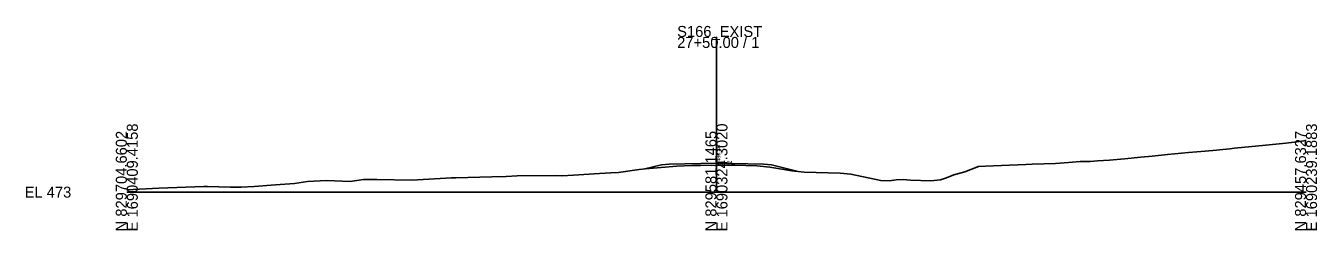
# Model space of a CAD drawing. Extents: x 1621104 to 1621433, y 1192880 to 1199414.
# Drawn here: x 1621104.2 to 1621432.7, y 1193379.5 to 1193431.6 of the extents above; entities that cross this region are included whole.
import ezdxf

# ---------------------------------------------------------------- set-up
doc = ezdxf.new("R2010")
doc.units = 0
for name, color, linetype in [('RD_GPK_XS_Cell', 7, 'Continuous'), ('RD_XS_EarthShd', 7, 'Continuous'), ('RD_XS_ExGround', 7, 'Continuous'), ('RD_XS_Pave', 7, 'Continuous'), ('RD_XS_TieSlope', 7, 'Continuous'), ('RD_XS_TX_Elev_EX', 7, 'Continuous'), ('RD_XS_TX_Elev_PR', 7, 'Continuous')]:
    doc.layers.add(name, color=color, linetype=linetype)

msp = doc.modelspace()

# ---------------------------------------------------------------- linework, layer by layer
at = {"layer": 'RD_GPK_XS_Cell'}
for p, q in [((1621279.86, 1193389.24), (1621279.86, 1193428.77)), ((1621129.86, 1193389.24), (1621279.86, 1193389.24)), ((1621279.86, 1193389.24), (1621429.86, 1193389.24))]:
    msp.add_line(p, q, dxfattribs=at)
at = {"layer": 'RD_XS_EarthShd'}
for p, q in [((1621267.86, 1193396.35), (1621265.86, 1193396.19)), ((1621291.86, 1193396.35), (1621293.86, 1193396.19))]:
    msp.add_line(p, q, dxfattribs=at)
at = {"layer": 'RD_XS_ExGround'}
msp.add_lwpolyline([(1621129.86, 1193389.85), (1621137.99, 1193390.24), (1621149.45, 1193390.64), (1621150.36, 1193390.64), (1621156.17, 1193390.47), (1621158.92, 1193390.52), (1621162.22, 1193390.64), (1621167.69, 1193391.08), (1621172.54, 1193391.4), (1621175.85, 1193391.92), (1621180.65, 1193392.22), (1621186.67, 1193391.99), (1621190.08, 1193392.46), (1621193.45, 1193392.47), (1621202.38, 1193392.27), (1621212.5, 1193392.88), (1621213.14, 1193392.91), (1621213.58, 1193392.88), (1621222.71, 1193393.17), (1621226.37, 1193393.24), (1621229.13, 1193393.43), (1621239.03, 1193393.44), (1621240.57, 1193393.43), (1621243.49, 1193393.55), (1621250.14, 1193394.02), (1621253, 1193394.14), (1621254.98, 1193394.27), (1621260.21, 1193395.03), (1621261.85, 1193395.15), (1621269.76, 1193395.87), (1621273.61, 1193396.06), (1621275.84, 1193396.06), (1621279.86, 1193396.08), (1621282.56, 1193396.09), (1621284.56, 1193396.13), (1621290.11, 1193395.94), (1621293.47, 1193395.62), (1621299.02, 1193394.7), (1621302.17, 1193394.31), (1621311.36, 1193394.11), (1621314.08, 1193393.81), (1621321.67, 1193392.18), (1621323.81, 1193392.11), (1621325.56, 1193392.35), (1621327.35, 1193392.49), (1621329.2, 1193392.29), (1621334.39, 1193392.12), (1621336.9, 1193392.34), (1621338.39, 1193392.9), (1621340.25, 1193393.66), (1621343.06, 1193394.4), (1621346.53, 1193395.77), (1621348.31, 1193395.83), (1621352.39, 1193395.99), (1621358.58, 1193396.28), (1621360.17, 1193396.37), (1621366.12, 1193396.56), (1621369.43, 1193396.81), (1621372.43, 1193397.04), (1621374.94, 1193397.05), (1621376.83, 1193397.19), (1621379.88, 1193397.37), (1621383.69, 1193397.74), (1621387.84, 1193398.15), (1621390.69, 1193398.43), (1621394.61, 1193398.81), (1621399.92, 1193399.3), (1621404.23, 1193399.71), (1621407.05, 1193399.94), (1621407.83, 1193400.01), (1621410.48, 1193400.27), (1621411.69, 1193400.41), (1621419.63, 1193401.24), (1621424.76, 1193401.73), (1621425.39, 1193401.79), (1621426.9, 1193401.99), (1621429.86, 1193402.41)], dxfattribs=at)
at = {"layer": 'RD_XS_Pave'}
for p, q in [((1621267.86, 1193396.35), (1621279.86, 1193396.59)), ((1621279.86, 1193396.59), (1621291.86, 1193396.35))]:
    msp.add_line(p, q, dxfattribs=at)
at = {"layer": 'RD_XS_TieSlope'}
for p, q in [((1621265.86, 1193396.19), (1621261.63, 1193395.14)), ((1621293.86, 1193396.19), (1621300.62, 1193394.5))]:
    msp.add_line(p, q, dxfattribs=at)

# ---------------------------------------------------------------- texts
at = {"layer": 'RD_GPK_XS_Cell'}
for s, p in [('S166_EXIST', (1621269.86, 1193428.77)), ('27+50.00 / 1', (1621269.86, 1193425.97)), ('EL 473', (1621103.86, 1193387.84))]:
    msp.add_text(s, height=2.8, dxfattribs=at).set_placement(p)
for s, p in [('N 829704.6602', (1621129.86, 1193379.24)), ('E 1690409.4158', (1621132.66, 1193379.24)), ('N 829581.1465', (1621279.86, 1193379.24)), ('E 1690324.3020', (1621282.66, 1193379.24)), ('N 829457.6327', (1621429.86, 1193379.24)), ('E 1690239.1883', (1621432.66, 1193379.24))]:
    msp.add_text(s, height=2.8, rotation=90, dxfattribs=at).set_placement(p)
at = {"layer": 'RD_XS_TX_Elev_EX'}
msp.add_text('479.84', height=1, dxfattribs=at).set_placement((1621279.76, 1193396.18))
at = {"layer": 'RD_XS_TX_Elev_PR'}
msp.add_text(' 480.36', height=1, rotation=90, dxfattribs=at).set_placement((1621280.86, 1193396.59))

doc.saveas('drawing.dxf')
